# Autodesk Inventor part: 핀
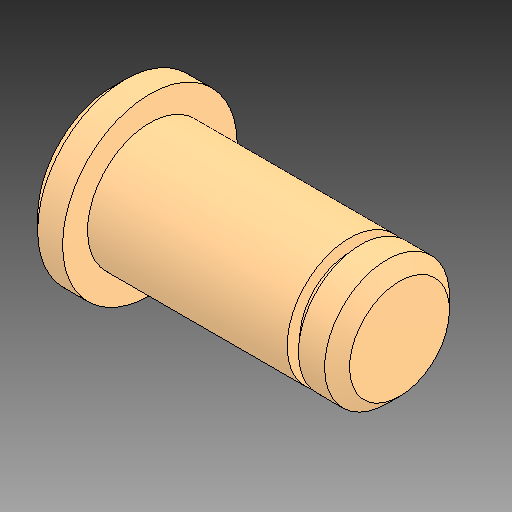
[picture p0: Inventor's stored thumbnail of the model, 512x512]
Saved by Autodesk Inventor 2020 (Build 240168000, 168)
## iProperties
Created: 2024-08
Part Number: 핀
Material: 강철, 탄소
Document SubType Name: Modeling
Designer: 1강의실14
Density: 7.85 g/cm^3
Appearance: 기본값
Author: jhkim
Sending System: Autodesk Inventor 2025
Preprocessor: ST-DEVELOPER v20
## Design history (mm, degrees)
feature "솔리드1"
node "솔리드2"
